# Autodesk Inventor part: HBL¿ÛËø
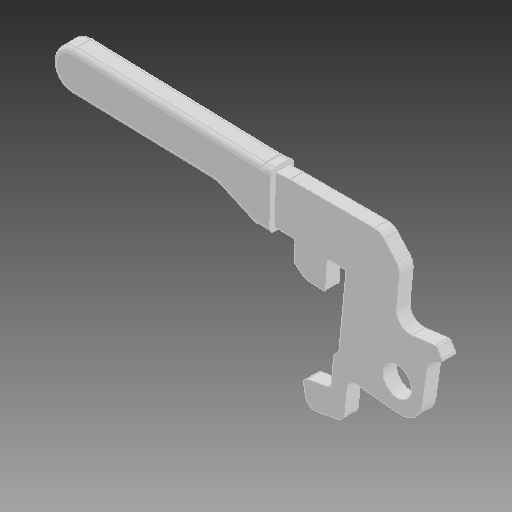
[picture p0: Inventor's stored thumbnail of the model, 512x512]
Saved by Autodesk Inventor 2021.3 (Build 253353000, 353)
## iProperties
Created: 2020-03
Part Number: HBL¿ÛËø
Material: Ogólny
Document SubType Name: Modeling
Designer: Przemyslaw Krecisz
Density: 1 g/cm^3
Appearance: Domyślna
Author: Przemyslaw Krecisz
Revision Number: ÈÎºÎ
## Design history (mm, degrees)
feature "Ô²½Ç1"
node "Bryła1"
